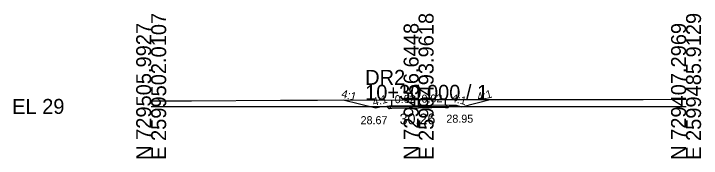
# Model space of a CAD drawing. Extents: x -26 to 1162, y -10 to 9515.
# Drawn here: x -25.7 to 102.8, y 1490.3 to 1517.3 of the extents above; entities that cross this region are included whole.
import ezdxf

# ---------------------------------------------------------------- set-up
doc = ezdxf.new("R2010")
doc.units = 0
for name, color, linetype in [('Exist Cross Section Cell', 7, 'Continuous'), ('Exist XS Center Line Elevation Label', 7, 'Continuous'), ('Exist XS Ground Line', 7, 'Continuous'), ('Prop XS Ditch Slope Text', 7, 'Continuous'), ('Prop XS Ditch Standard Text', 7, 'Continuous'), ('Prop XS Dump Level', 7, 'Continuous'), ('Prop XS EOT Tick Mark', 7, 'Continuous'), ('Prop XS Finish Grade', 7, 'Continuous'), ('Prop XS Finish Grade Earthwork', 7, 'Continuous'), ('Prop XS Finish Grade Pavement', 7, 'Continuous'), ('Prop XS Pvmt Edge Slope', 7, 'Continuous'), ('Prop XS SE Text', 7, 'Continuous'), ('Prop XS Side Slope Text', 7, 'Continuous'), ('Prop XS Subgrade Earthwork', 7, 'Continuous')]:
    doc.layers.add(name, color=color, linetype=linetype)

msp = doc.modelspace()

# ---------------------------------------------------------------- linework, layer by layer
at = {"layer": 'Exist Cross Section Cell'}
for p, q in [((50, 1500), (50, 1504.03)), ((0, 1500), (50, 1500)), ((50, 1500), (100, 1500))]:
    msp.add_line(p, q, dxfattribs=at)
at = {"layer": 'Exist XS Ground Line'}
msp.add_lwpolyline([(0, 1501.05), (3.69, 1501.05), (7.52, 1501.07), (24.17, 1501.14), (31.09, 1501.17), (47.2, 1501.25), (50, 1501.26), (61.75, 1501.3), (66.26, 1501.3), (86.25, 1501.32), (91.96, 1501.32), (99.66, 1501.34), (100, 1501.34)], dxfattribs=at)
at = {"layer": 'Prop XS Dump Level'}
for p, q in [((45, 1500.08), (50, 1500.18)), ((50, 1500.18), (55, 1500.28))]:
    msp.add_line(p, q, dxfattribs=at)
at = {"layer": 'Prop XS EOT Tick Mark'}
for p, q in [((55, 1500.28), (55, 1501.28)), ((45, 1500.08), (45, 1501.08))]:
    msp.add_line(p, q, dxfattribs=at)
at = {"layer": 'Prop XS Finish Grade'}
for p, q in [((45, 1500.08), (44.05, 1500)), ((55, 1500.28), (55.95, 1500.24))]:
    msp.add_line(p, q, dxfattribs=at)
at = {"layer": 'Prop XS Finish Grade Earthwork'}
for p, q in [((58, 1499.95), (63.39, 1501.3)), ((42, 1499.67), (35.91, 1501.19)), ((44.05, 1500), (43, 1499.92)), ((55.95, 1500.24), (57, 1500.2)), ((57, 1500.2), (58, 1499.95)), ((43, 1499.92), (42, 1499.67))]:
    msp.add_line(p, q, dxfattribs=at)
at = {"layer": 'Prop XS Finish Grade Pavement'}
for p, q in [((45, 1500.08), (50, 1500.18)), ((50, 1500.18), (55, 1500.28))]:
    msp.add_line(p, q, dxfattribs=at)
at = {"layer": 'Prop XS Pvmt Edge Slope'}
for p, q in [((44.49, 1499.57), (44.05, 1500)), ((45, 1500.08), (44.49, 1499.57)), ((55, 1500.28), (55.49, 1499.79)), ((55.49, 1499.79), (55.95, 1500.24))]:
    msp.add_line(p, q, dxfattribs=at)
at = {"layer": 'Prop XS Subgrade Earthwork'}
for p, q in [((44.49, 1499.57), (44.05, 1500)), ((55.49, 1499.79), (55.95, 1500.24)), ((45, 1499.58), (44.49, 1499.57)), ((50, 1499.68), (45, 1499.58)), ((55, 1499.78), (50, 1499.68)), ((55, 1499.78), (55.49, 1499.79))]:
    msp.add_line(p, q, dxfattribs=at)

# ---------------------------------------------------------------- texts
at = {"layer": 'Exist Cross Section Cell'}
for s, p in [('E 2599502.0107', (2.8, 1490)), ('E 2599493.9618', (52.8, 1490)), ('E 2599485.9129', (102.8, 1490)), ('N 729505.9927', (0, 1490)), ('N 729456.6448', (50, 1490)), ('N 729407.2969', (100, 1490))]:
    msp.add_text(s, height=2.8, rotation=90, dxfattribs=at).set_placement(p)
for s, p in [('DR2', (40, 1504.03)), ('10+30.000 / 1', (40, 1501.23)), ('EL 29', (-26, 1498.6))]:
    msp.add_text(s, height=2.8, dxfattribs=at).set_placement(p)
at = {"layer": 'Exist XS Center Line Elevation Label'}
msp.add_text('30.26', height=2, dxfattribs=at).set_placement((46.44, 1496.66))
at = {"layer": 'Prop XS Ditch Slope Text'}
for rotation, p in [(14.0362, (41.58, 1500.05)), (345.9638, (56.01, 1500.92))]:
    msp.add_text('4:1', height=1.5, rotation=rotation, dxfattribs=at).set_placement(p)
at = {"layer": 'Prop XS Ditch Standard Text'}
for s, p in [('28.67', (39.15, 1496.67)), ('28.95', (55.19, 1496.95))]:
    msp.add_text(s, height=1.5, dxfattribs=at).set_placement(p)
at = {"layer": 'Prop XS Dump Level'}
for p in [(57, 1500.16), (43, 1499.88)]:
    msp.add_text('Case1', height=0.04, dxfattribs=at).set_placement(p)
at = {"layer": 'Prop XS SE Text'}
for p in [(45.55, 1500.59), (50.55, 1500.69)]:
    msp.add_text('0.02', height=1.5, rotation=1.1458, dxfattribs=at).set_placement(p)
at = {"layer": 'Prop XS Side Slope Text'}
for rotation, p in [(345.9638, (35.46, 1501.71)), (14.0362, (61.14, 1501.02))]:
    msp.add_text('4:1', height=1.5, rotation=rotation, dxfattribs=at).set_placement(p)

doc.saveas('drawing.dxf')
